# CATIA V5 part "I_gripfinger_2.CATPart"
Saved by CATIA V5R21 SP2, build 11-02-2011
Part number: I_gripfinger_2
Bounding box of the stored display mesh (mm): x -20 to 20, y -5 to 5, z 0 to 60
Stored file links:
  \\ariel.ad.iei.liu.se\LAB_DELMIA\A1_LAB_INTRO_2011\LAB_INTRO_DATA_2011\I_gripfinger_2.CATPart
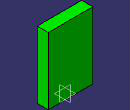
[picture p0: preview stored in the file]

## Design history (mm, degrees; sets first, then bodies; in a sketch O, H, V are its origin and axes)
Body1 (main body)
  Sketch1 on xy-plane, origin (0, 0, 0), H (1, 0, 0), V (0, 1, 0)
    line L1 (-20, -5) -> (20, -5)
    line L2 (20, -5) -> (20, 5)
    line L3 (20, 5) -> (-20, 5)
    line L4 (-20, 5) -> (-20, -5)
    horizontal: L1 H, L3 H
    vertical: L2 V, L4 V
  Pad1: profile Sketch1, direction (0, 0, 1), length 60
